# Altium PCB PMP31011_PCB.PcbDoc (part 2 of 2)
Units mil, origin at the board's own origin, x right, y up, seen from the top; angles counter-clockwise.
Board outline 3287.4 x 3750 mil, 4 copper layers (Top Layer, GND, Signal Layer, Bottom Layer), stack 84.834 mil thick; 100 components, 44 nets, 235 pads, 404 vias.
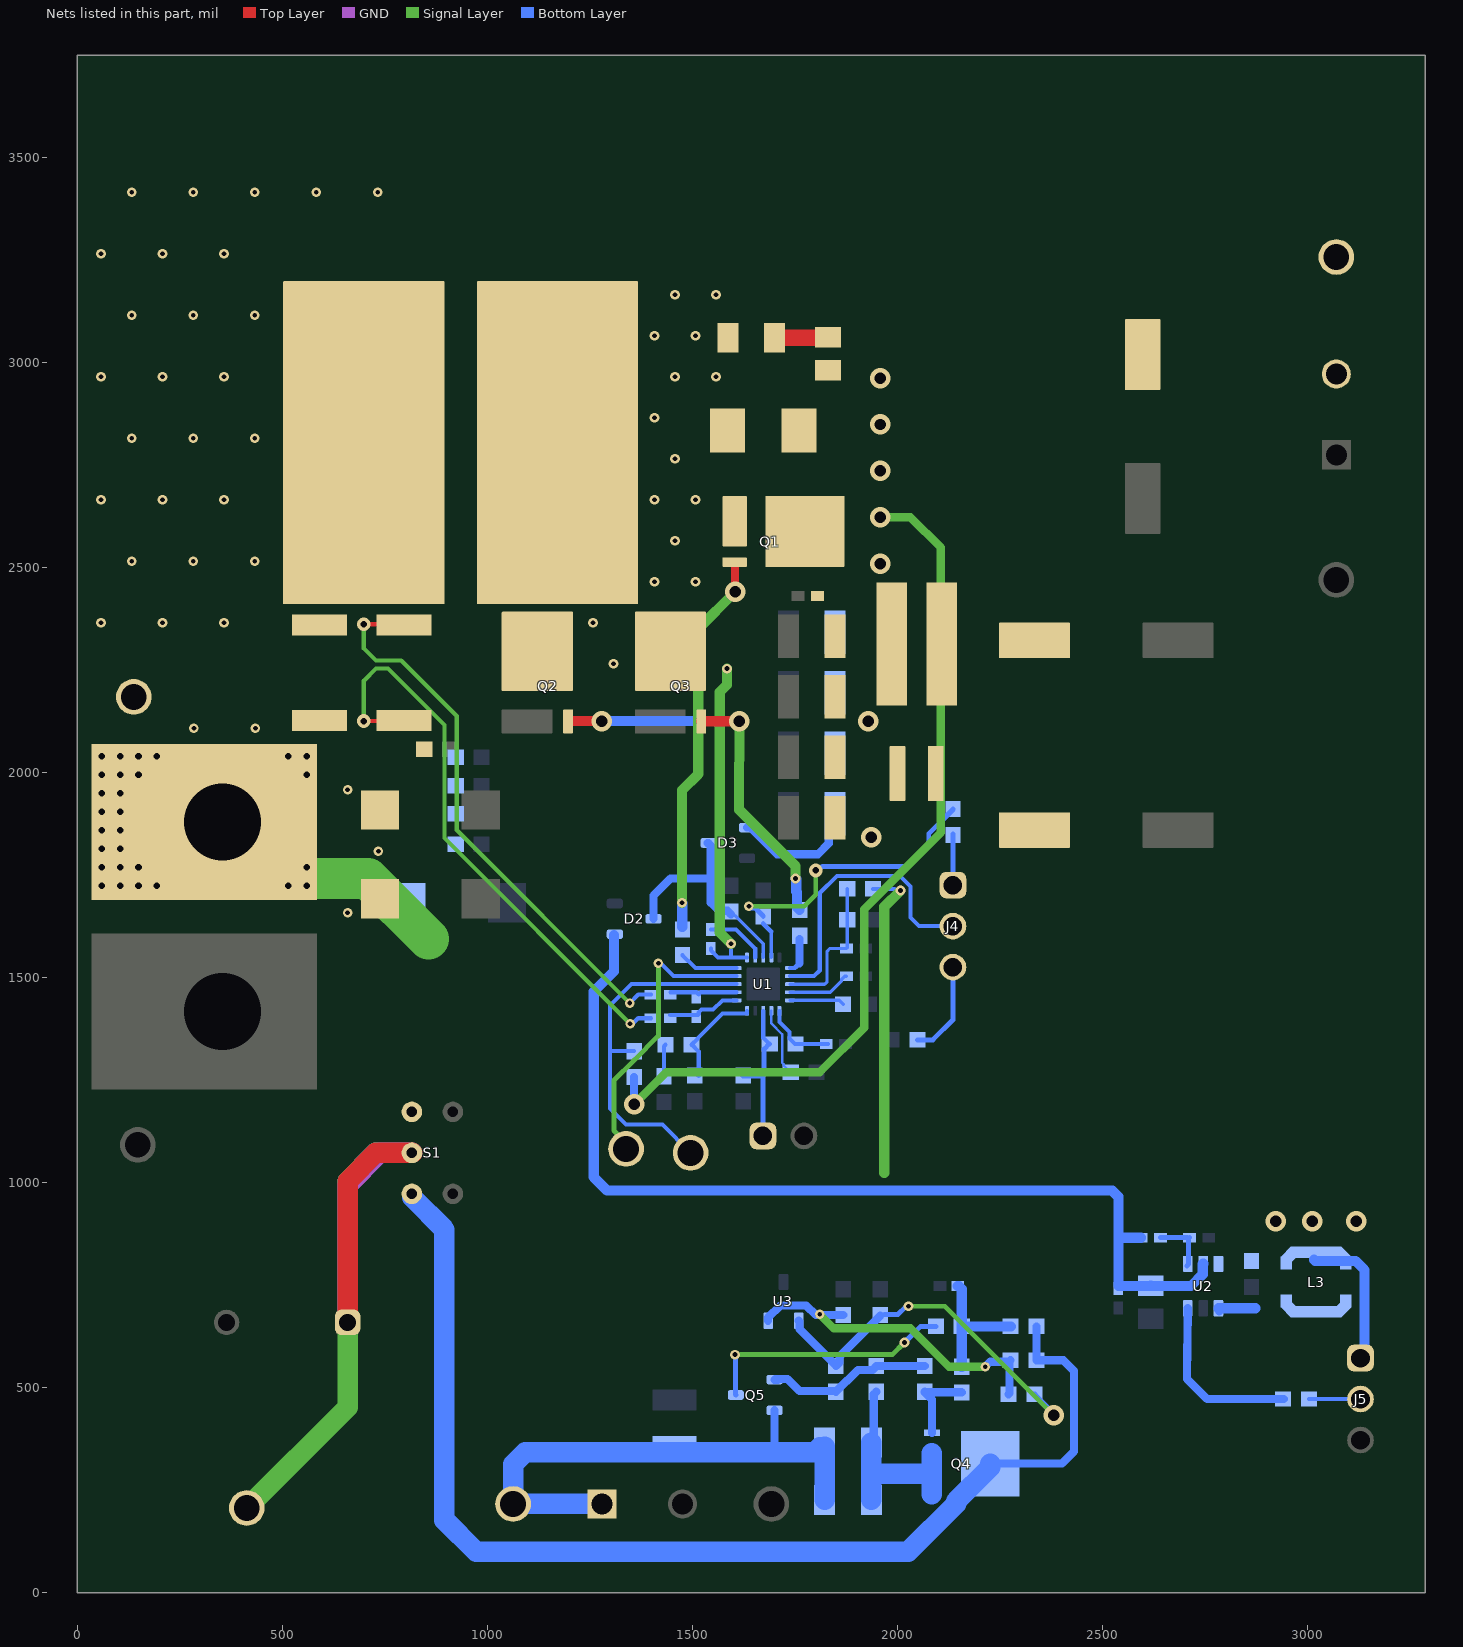
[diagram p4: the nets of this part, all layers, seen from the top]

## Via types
v1: diameter 23.62, hole 11.81, Top Layer to Bottom Layer, 298 vias
v2: diameter 32, hole 16, Top Layer to Bottom Layer, 56 vias
v3: diameter 50, hole 28, Top Layer to Bottom Layer, 37 vias
v4: diameter 23.62, hole 11.81, Top Layer to Bottom Layer, tented both sides, 6 vias
v5: diameter 196.85, hole 118.11, Top Layer to Bottom Layer, 4 vias
v6: diameter 34, hole 16, Top Layer to Bottom Layer, 3 vias

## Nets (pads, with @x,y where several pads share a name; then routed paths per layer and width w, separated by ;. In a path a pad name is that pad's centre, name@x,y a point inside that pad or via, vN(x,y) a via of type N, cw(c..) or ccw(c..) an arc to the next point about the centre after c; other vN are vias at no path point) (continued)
CSN: L2.1 R2.1 R3.1 R11.2 | length 1394.2
  Top Layer w10: v6(698.82,2362.2) R3.1@797.24,2362.2
  Signal Layer w10: v6@703.41,2357.61 v6(698.82,2362.2) 698.82,2303.15 728.35,2273.62 790.28,2273.62 925.54,2138.36 925.54,1859.89 v1(1347.38,1438.06)
  Bottom Layer w10: v1(1347.38,1438.06) 1347.64,1438.06 1368.3,1458.71 R11.2@1399.05,1458.71
  other v1: 58,2366 208,2366 358,2366 133,2516 283,2516 433,2516 58,2666 208,2666 358,2666 133,2816 283,2816 433,2816 58,2966 208,2966 358,2966 133,3116 283,3116 433,3116 58,3266 208,3266 358,3266 133,3416 283,3416 433,3416 583,3416 733,3416
CSP: C2.1 C3.1 C4.1 C5.1 C6.1 C7.1 C8.1 C9.1 C34.1 J5.1 L3.1 R2.2 R3.2 R6.2 R10.2 S1.4 T1.1 TP1.1 U2.6 | length 3118.8
  Top Layer w10: v6(698.82,2125.98) R3.2@797.24,2125.98
  Signal Layer w10: v6(698.82,2125.98) 698.82,2224.41 728.35,2253.94 757.87,2253.94 895.67,2116.14 895.67,1840.55 v1(1348.43,1387.8)
  Signal Layer w25: 1968.5,1023.62 1968.5,1673.23 v1(2007.87,1712.6)
  Signal Layer w100: T1.1@481.3,1742.13 708.66,1742.13 856.3,1594.49
  Bottom Layer w10: v1(1348.43,1387.8) 1354.8,1387.8 1368.3,1401.29 R10.2@1399.05,1401.29 ; R6.2@1940.95,1716.75 1993.88,1716.75 1998.03,1712.6 v1(2007.87,1712.6)
  Bottom Layer w25: 3016.76,812.03 3019.41,809.38 3117.79,809.38 3139.76,787.4 J5.1@3139.76,572.44 ; J5.1@3129.92,570.87 J5.1@3129.92,572.44
  Bottom Layer w50: T1.1@344.49,1878.94 T1.1@432.09,1791.34
  other v1: 659.45,1658.66 734.45,1808.66 659.45,1958.66 284.45,2108.66 434.45,2108.66
  other v2: 59.33,1724.92 104.33,1724.92 149.33,1724.92 194.33,1724.92 514.33,1724.92 559.33,1724.92 59.33,1769.92 104.33,1769.92 149.33,1769.92 559.33,1769.92 59.33,1814.92 104.33,1814.92 59.33,1859.92 104.33,1859.92 59.33,1904.92 104.33,1904.92 59.33,1949.92 104.33,1949.92 59.33,1994.92 104.33,1994.92 149.33,1994.92 559.33,1994.92 59.33,2039.92 104.33,2039.92 149.33,2039.92 194.33,2039.92 514.33,2039.92 559.33,2039.92
  other v3: 2923.23,905.51 3011.81,905.51 3120.08,905.51
HO: R5.1 U1.5 | length 145.5
  Bottom Layer w10: R5.1@1476.38,1555.12 1476.38,1554.13 1490.08,1540.43 1491.06,1540.43 1507.82,1523.68 U1.5@1608.27,1523.68
MODE: J4.2 U1.12 | length 694.9
  Bottom Layer w10: U1.12@1738.19,1503.99 1797.3,1503.99 1811.02,1517.72 1811.02,1706.41 1852.94,1748.32 2007.06,1748.32 2032.56,1722.82 2032.56,1646.53 2053.1,1625.98 J4.2@2125.98,1625.98
NetC1_2: C1.2 R1.2 | length 119.6
  Top Layer w25: R1.2@1700.79,3061.02 1700.79,3050.2 R1.2@1701.13,3049.79
  Top Layer w40: R1.2@1722.44,3061.02 C1.2@1830.71,3061.02
NetC22_1: C22.1 D2.3 D3.3 U1.8 | length 556.7
  Bottom Layer w8: C22.1@1604.33,1651.63 1673.23,1582.73 U1.8@1673.23,1549.27
  Bottom Layer w20: D2.3@1405.51,1643.7 1405.51,1700.79 1446.85,1742.13 1545.28,1742.13 ; D3.3@1539.37,1828.74 1537.4,1828.74 1545.28,1820.87 1545.28,1742.13 ; C22.1@1594.49,1654.68 1585.79,1663.39 1564.96,1663.39 1545.28,1683.07 1545.28,1742.13
NetC23_1: C23.1 U1.7 | length 149.7
  Bottom Layer w10: C23.1@1545.28,1618.16 1606.73,1618.16 1653.54,1571.35 U1.7@1653.54,1549.27
NetC23_2: C23.2 D1.2 L2.2 Q1.1-2-3 Q2.5-6-7-8 Q3.5-6-7-8 R1.1 U1.6 | length 825.8
  Signal Layer w25: v1(1584.65,2253.94) 1584.65,2214.57 1566.96,2196.88 1566.96,1610.26 v1(1594.49,1582.73)
  Bottom Layer w10: C23.2@1545.28,1570.92 1545.28,1566.98 1562.99,1549.27 U1.6@1633.86,1549.27 ; v1@1589.9,1578.14 v1(1594.49,1582.73) 1594.49,1553.2
  other v1: 1308,2266 1258,2366 1408,2466 1508,2466 1458,2566 1408,2666 1508,2666 1458,2766 1408,2866 1458,2966 1558,2966 1408,3066 1508,3066 1458,3166 1558,3166
NetC24_1: C24.1 R6.1 R9.2 U1.13 | length 363.8
  Bottom Layer w8: U1.13@1738.19,1484.31 1822.68,1484.31 1828.74,1490.37 1828.74,1564.96 1835.13,1571.35 C24.1@1875.98,1571.35 1877.95,1573.32 R9.2@1877.95,1641.79 R6.1@1877.95,1716.75
NetC25_1: C25.1 S1.5 TP6.1 | length 2659.5
  Top Layer w50: C25.1@659.45,669.29 659.45,1003.94 728.35,1072.83 S1.5@816.14,1072.83 S1.5@816.93,1072.83
  GND w50: C25.1@659.45,659.45 659.45,994.09 738.19,1072.83 S1.5@816.14,1072.83
  Signal Layer w50: TP6.1@413.39,196.85 TP6.1@423.23,196.85 ; TP6.1@413.39,206.69 659.45,452.76 C25.1@659.45,659.45 659.45,1003.94 728.35,1072.83 S1.5@816.14,1072.83
  Bottom Layer w50: C25.1@659.45,669.29 659.45,1003.94 728.35,1072.83 S1.5@816.14,1072.83 S1.5@816.93,1072.83
NetC26_1: C26.1 R10.1 U1.1 | length 179
  Bottom Layer w10: R10.1@1446.29,1409.5 1513.78,1409.5 1515.75,1411.47 1515.75,1415.41 1522.56,1422.22 1550.65,1422.22 1573.37,1444.93 U1.1@1608.27,1444.93
NetC26_2: C26.2 R11.1 U1.2 | length 166.3
  Bottom Layer w10: R11.1@1446.85,1464.62 1509.84,1464.62 1515.75,1458.71 1521.65,1464.62 U1.2@1608.27,1464.62
NetC27_1: C27.1 U1.17 | length 171.8
  Bottom Layer w6: U1.17@1692.91,1419.34 1692.91,1388.41 1719.54,1361.79 1719.54,1292.28 1723.47,1288.34 1723.47,1285.39 1739.17,1269.68 C27.1@1740.16,1269.68 C27.1@1742.13,1269.68
NetC29_1: C29.1 R13.2 U1.20 | length 258.5
  Bottom Layer w10: R13.2@1497.84,1336.67 R13.2@1498.82,1336.67 ; C29.1@1515.75,1259.9 1515.75,1319.74 R13.2@1498.82,1336.67 ; U1.20@1633.86,1419.34 1633.86,1412.81 1633.58,1412.53 1573.71,1412.53 1512.52,1351.35 1512.52,1350.37 R13.2@1498.82,1336.67
NetC30_1: C30.1 R16.2 U1.16 | length 175.4
  Bottom Layer w10: U1.16@1712.6,1419.34 1712.6,1392.53 1737.28,1367.85 1737.28,1352.28 R16.2@1750.98,1338.58 ; R16.2@1751.97,1338.58 C30.1@1826.77,1338.58 C30.1@1830.71,1338.58
NetC31_1: C31.1 R13.1 | length 78.3
  Bottom Layer w10: C31.1@1431.1,1259.9 1431.1,1332.92 R13.1@1434.85,1336.67
NetC32_1: C32.1 J2.1 Q5.2 R15.1 R17.1 TP7.1 | length 1331.3
  Bottom Layer w20: Q5.2@1700.79,444.88 1700.79,350.39 1708.66,342.52
  Bottom Layer w25: R15.1@1822.83,355.61 R15.1@1822.83,366.14
  Bottom Layer w50: TP7.1@1062.99,216.54 J2.1@1279.53,216.54 ; TP7.1@1062.99,221.13 1062.99,313.23 1092.28,342.52 1708.66,342.52 1799.21,342.52 1811.42,354.72 1822.24,354.72 R15.1@1822.83,355.32 ; R17.1@1822.83,226.38 R15.1@1822.83,355.32 ; R15.1@1822.83,355.61 R15.1@1822.83,355.32
NetC33_1: C33.1 C37.1 R23.1 U3.1 | length 918.6
  Signal Layer w12: v1(2027.56,698.82) 2116.14,698.82 v3(2381.89,433.07)
  Bottom Layer w12: C37.1@1968.5,679.13 2001.92,679.13 2021.61,698.82 v1(2027.56,698.82) ; C33.1@2334.65,484.25 2335.63,484.25 2381.89,437.99 v3(2381.89,433.07)
  Bottom Layer w20: U3.1@1759.84,663.39 1761.65,661.57 1761.65,642.87 1850.39,554.13 R23.1@1850.39,553.15 1859.09,561.85 1859.09,576.61 C37.1@1958.66,676.18
NetC33_2: C33.2 R22.1 R29.2 U3.2 | length 810
  Signal Layer w20: v1(1811.02,679.13) 1845.05,645.11 2032.16,645.11 2126.09,551.18 v1(2214.57,551.18)
  Bottom Layer w20: U3.2@1685.04,663.39 1685.04,671.26 1714.72,700.95 1777.88,700.95 v1@1801.66,677.17 ; v1@1811.02,677.17 R29.2@1868.11,677.17 ; v1(2214.57,551.18) 2226.89,563.5 2273.15,563.5 R22.1@2274.11,564.47 ; C33.2@2271.65,484.25 2274.11,486.71 R22.1@2274.11,564.47 ; R22.1@2276.57,566.93 R22.1@2274.11,564.47
NetD4_1: D4.1 R21.1 R24.1 R25.2 | length 321.5
  Bottom Layer w25: D4.1@2147.64,748.03 2150.2,748.03 2157.48,740.75 R25.2@2157.48,649.61 ; R24.1@2157.48,551.18 R25.2@2157.48,649.61 ; R21.1@2276.57,649.61 R25.2@2157.48,649.61
NetJ3_1: J3.1 R16.1 R20.2 U1.18 | length 372
  Bottom Layer w10: U1.18@1673.23,1419.34 1673.23,1353.35 1687.99,1338.58 R16.1@1688.98,1338.58
  Bottom Layer w12: R20.2@1624.02,1259.84 1673.23,1259.84 ; 1671.26,1263.78 1672.44,1262.6 ; J3.1@1673.23,1114.17 1672.44,1114.96 1672.44,1262.6 ; 1673.23,1261.81 1672.44,1262.6 ; R16.1@1688.98,1338.58 1687.99,1338.58 1675.29,1325.88 1675.29,1265.45 1672.44,1262.6
NetJ4_1: J4.1 R30.1 | length 124.4
  Bottom Layer w12: J4.1@2135.83,1725.98 R30.1@2135.83,1848.43 R30.1@2135.83,1850.39
NetJ4_3: J4.3 R32.2 | length 239.6
  Bottom Layer w12: R32.2@2049.21,1348.43 2086.9,1348.43 2135.83,1397.35 2135.83,1516.14 J4.3@2125.98,1525.98
NetJ5_2: J5.2 R26.2 | length 126
  Bottom Layer w10: R26.2@3003.94,472.44 J5.2@3129.92,472.44
NetL3_2: L3.2 U2.1 | length 97.7
  Bottom Layer w20: U2.1@2783.46,693.9 2783.46,688.49 U2.1@2785.28,686.68
  Bottom Layer w25: U2.1@2783.46,693.9 2873.23,693.9
NetQ1_4: Q1.4 R5.2 | length 944
  Top Layer w20: Q1.4@1603.54,2513.58 1603.94,2513.19 1603.94,2441.34 v3(1604.33,2440.94)
  Signal Layer w25: v1(1475.03,1683.07) 1475.03,1957.32 1514.4,1996.68 1514.4,2351.01 v3(1604.33,2440.94)
  Bottom Layer w25: v1(1475.03,1683.07) 1475.7,1682.4 1475.7,1624.69 R5.2@1476.38,1624.02
NetQ2_4: Q2.4 Q3.4 R8.1 | length 1028.4
  Top Layer w25: Q2.4@1200.79,2125.98 v3(1279.53,2125.98) ; Q3.4@1521.85,2125.2 1522.24,2125.59 1613.78,2125.59 v3(1614.17,2125.98)
  Signal Layer w25: v3(1614.17,2125.98) 1615.52,2124.63 1614.17,1929.13 1614.17,1909.45 1751.97,1771.65 v1(1751.97,1742.13)
  Bottom Layer w25: v3(1279.53,2125.98) v3(1614.17,2125.98) ; v1(1751.97,1742.13) 1753.69,1740.4 1753.69,1710.88 1755.61,1708.96 1755.61,1671.56 R8.1@1761.81,1665.35
NetQ4_1: Q4.1 Q4.2 Q4.3 R15.2 R17.2 R18.2 | length 516.1
  Bottom Layer w20: R15.2@1937.01,366.14 1942.91,372.05 1942.91,484.25 R18.2@1948.82,490.16
  Bottom Layer w50: R17.2@1937.01,226.38 1937.01,289.96 ; R15.2@1937.01,366.14 1937.01,289.96 ; Q4.1@2084.45,239.96 Q4.2@2084.45,289.96 ; Q4.3@2084.45,339.96 Q4.2@2084.45,289.96 ; 1937.01,289.96 Q4.2@2084.45,289.96
NetQ4_4: Q4.4 R19.2 R24.2 | length 198.8
  Bottom Layer w20: Q4.4@2084.45,389.96 2084.45,471.65 2066.93,489.17 R19.2@2066.93,490.16 2067.91,489.17 2156.5,489.17 R24.2@2157.48,488.19
NetQ4_5: Q4.5 R21.2 R22.2 S1.6 | length 2879
  Bottom Layer w20: Q4.5@2226.57,314.96 2401.57,314.96 2431.1,344.49 2431.1,541.34 2405.51,566.93 R22.2@2339.57,566.93 R21.2@2339.57,649.61
  Bottom Layer w50: S1.6@816.93,964.57 895.67,885.83 895.67,551.18 895.57,177.27 972.84,100 2026.33,100 2143.78,217.44 2143.78,223.68 2226.57,306.48 Q4.5@2226.57,314.96
NetQ5_1: Q5.1 R18.1 R19.1 R23.2 | length 411.5
  Bottom Layer w20: Q5.1@1700.79,519.69 Q5.1@1708.66,519.69 ; Q5.1@1702.76,521.65 1732.28,521.65 1761.81,492.13 R23.2@1850.39,492.13 ; R23.2@1850.39,490.16 1850.39,491.14 1874.84,515.59 1876.5,515.59 1904.37,543.46 1940.12,543.46 1948.82,552.17 R18.1@1948.82,553.15 R19.1@2066.93,553.15
NetQ5_3: Q5.3 R25.1 | length 617.9
  Signal Layer w12: v1(1604.33,580.71) 1988.19,580.71 v1(2017.72,610.24)
  Bottom Layer w12: v1(1604.33,580.71) 1605.32,579.72 1605.32,483.27 Q5.3@1606.3,482.28 ; v1(2017.72,610.24) 2057.09,649.61 R25.1@2094.49,649.61
NetR7_1: R7.1 TP5.1 U1.3 | length 883.3
  Bottom Layer w10: R7.1@1358.27,1320.87 1301.18,1320.87 1299.21,1318.9 ; TP5.1@1496.06,1072.83 1427.17,1141.73 1338.58,1141.73 1299.21,1181.1 1299.21,1318.9 ; U1.3@1608.27,1484.31 1351.38,1484.31 1299.21,1432.14 1299.21,1318.9
NetR8_2: R8.2 U1.11 | length 87.5
  Bottom Layer w10: U1.11@1738.19,1523.68 1738.46,1523.95 1750.33,1523.95 1751.97,1525.59
  Bottom Layer w12: 1751.97,1525.59 1761.81,1535.43
  Bottom Layer w20: 1761.81,1535.43 R8.2@1761.81,1594.49
NetR12_2: R12.2 U1.15 | length 134
  Bottom Layer w8: U1.15@1738.19,1444.93 1858.27,1444.93 R12.2@1868.11,1435.09
NetR14_2: R14.2 U1.14 | length 156.4
  Bottom Layer w8: U1.14@1738.19,1464.62 1836.61,1464.62 1864.24,1492.24 1864.24,1496.18 1872.05,1503.99 R14.2@1875.98,1503.99
NetR26_1: R26.1 U2.3 | length 428.9
  Bottom Layer w20: U2.3@2708.66,693.9 2706.69,521.65 2755.91,472.44 R26.1@2940.94,472.44 R26.1@2942.91,472.44
NetR28_1: R28.1 R31.2 U2.4 | length 136.3
  Bottom Layer w12: R28.1@2641.73,866.14 R31.2@2706.69,866.14 ; U2.4@2706.69,797.24 2710.63,801.18 2710.63,864.17 R31.2@2712.6,866.14
STATUS: TP9.1 U1.4 | length 776.8
  Top Layer w20: TP9.1@1338.58,1053.15 TP9.1@1338.58,1082.68
  Signal Layer w12: TP9.1@1331.2,1082.68 1331.2,1105.06 1309.06,1127.21 1309.06,1250 1358.27,1299.21 1417.32,1358.27 v1(1417.32,1535.43) ; TP9.1@1338.58,1072.83 TP9.1@1338.58,1082.68
  Signal Layer w20: TP9.1@1338.58,1053.15 1351.15,1065.71 TP9.1@1365.39,1065.71
  Bottom Layer w10: v1@1422.67,1535.49 1454.16,1503.99 U1.4@1608.27,1503.99
VAUX: C35.1 C36.1 D2.1 R28.2 U2.5 | length 2427
  Bottom Layer w25: D2.1@1309.06,1604.33 1309.06,1515.75 1259.84,1466.54 1259.84,1013.78 1292.72,980.91 2524.73,980.91 2539.37,966.26 2539.37,866.14 ; R28.2@2594.49,866.14 2539.37,866.14 ; C36.1@2618.11,748.03 2716.54,748.03 2745.37,776.87 2745.37,801.48 U2.5@2746.06,802.17 ; C36.1@2618.11,748.66 2539.37,748.03 2539.37,866.14
VCC: C28.1 R30.2 U1.9 | length 786.4
  Signal Layer w12: v1(1638.06,1674.32) 1772.75,1674.32 1801.18,1702.76 v6(1801.18,1761.81)
  Bottom Layer w8: 1692.72,1612.26 1692.91,1612.07 U1.9@1692.91,1549.27
  Bottom Layer w12: v1(1638.06,1674.32) 1642.27,1670.11 1653.76,1670.11 1673.23,1650.64 C28.1@1673.23,1649.66 ; C28.1@1673.23,1631.94 1692.72,1612.45 1692.72,1612.26 ; v6@1801.18,1771.65 1806.81,1766.02 1811.34,1766.02 1816.98,1771.65 2027.56,1771.65 2076.77,1820.87 2076.77,1851.38 2135.83,1910.43 R30.2@2135.83,1911.42
VOUT: C1.1 C10.1 C11.1 C12.1 C13.1 C14.1 C15.1 C16.1 C17.1 C18.1 D1.1 D3.1 L1.1 Q1.5-6-7-8 R4.1 R7.2 | length 2438.8
  Signal Layer w20: v3(1358.27,1190.94) 1399.31,1231.99 1437.01,1269.68 1811.02,1269.68 1919.29,1377.95 1919.29,1666.97 2106.3,1853.98 2106.3,2549.21 2032.48,2623.03 v3(1958.66,2623.03)
  Bottom Layer w20: v3(1358.27,1190.94) R7.2@1358.27,1257.87 ; D3.1@1633.86,1866.14 1641.73,1866.14 1706.69,1801.18 1806.79,1801.18 1832.83,1827.23 1832.83,1872.2 C18.1@1850.39,1889.76
  other v3: 1936.94,1842.59 1929.13,2125.98 1958.66,2509.84 1958.66,2736.22 1958.66,2849.41 1958.66,2962.6
VOUT_FLT: C19.2 C20.2 C21.2 J1.2 L1.2 R4.2 TP2.1
pads on no net: D2.2 D3.2 S1.1 S1.3
copper on no net:
  other v3: 2145.67,3336.61
  other v5: 147.64,147.64 3139.76,147.64 147.64,3602.36 3139.76,3602.36

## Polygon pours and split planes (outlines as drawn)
NetC23_2 on Top Layer "TOP_LAYER_NETC23_2_P010" (solid, pour order 10): 974.41,3248.03 1003.94,3277.56 1604.33,3277.56 1633.86,3248.03 1633.86,2480.32 1614.17,2460.63 1614.17,2234.25 1564.96,2185.04 1043.31,2185.04 974.41,2253.94
CSP on Top Layer "TOP_LAYER_CSP_P004" (solid, remove dead copper, pour order 4): 19.68,2234.25 39.37,2253.94 787.4,2253.94 866.14,2175.2 866.14,1690.55 798.24,1643.7 29.53,1643.7 29.53,2057.08 19.69,2057.08
CSN on Top Layer "TOP_LAYER_CSN_P009" (solid, pour order 9): 885.83,2372.05 885.83,2322.83 859.25,2296.26 56.1,2296.26 29.53,2322.83 29.53,3533.46 78.74,3582.68 836.61,3582.68 885.83,3533.46
NetC1_2 on Top Layer "TOP_LAYER_NETC1_2_P011" (solid, pour order 11): 1673.23,3553.15 1702.76,3582.68 1988.19,3582.68 2037.4,3533.47 2037.4,3051.18 2007.87,3021.65 1673.23,3021.65
VOUT_FLT on Top Layer "TOP_LAYER_VOUT_FLT_P002" (solid, pour order 2): 2062.95,3405.51 3080.71,3405.51 3149.61,3336.61 3149.61,2864.17 2578.74,2864.17 2500,2785.43 2500,1692.91 2460.63,1653.54 2096.42,1653.54 2062.95,1687.01
VOUT on Top Layer "TOP_LAYER_VOUT_P003" (solid, pour order 3): 1673.23,2981.65 1703.23,3011.65 2007.79,3011.65 2031.53,2987.91 2031.53,1797.81 2005.37,1771.65 1821.02,1771.65 1791.49,1801.18 1791.49,2460.48 1774.75,2477.22 1692.74,2477.22 1673.23,2496.73
AGND on Top Layer "TOP_LAYER_AGND_P023" (solid, pour order 23): 2716.54,3385.83 2401.57,3385.83 2342.52,3385.83 2234.25,3385.83 2214.57,3366.14 2214.57,3051.18 2165.35,3001.97 2057.09,3001.97 2057.09,2480.32 1690.95,2480.32 1633.86,2419.15 1633.86,2165.35 1624.02,2155.51 925.2,2155.51 885.83,2116.14 885.83,1675.71 810.14,1614.17 19.68,1614.17 19.68,108.27 68.9,59.06 68.9,39.37 3188.98,39.37 3248.03,98.43 3248.03,3287.4 3149.61,3385.83
NetC23_2 on Bottom Layer "BOTTOM_LAYER_NETC23_2_P013" (solid, pour order 13): 974.41,3248.03 1003.94,3277.56 1604.33,3277.56 1633.86,3248.03 1633.86,2480.32 1614.17,2460.63 1614.17,2234.25 1564.96,2185.04 1043.31,2185.04 974.41,2253.94
CSN on Bottom Layer "BOTTOM_LAYER_CSN_P015" (solid, pour order 15): 885.83,2372.05 885.83,2322.83 859.25,2296.26 56.1,2296.26 29.53,2322.83 29.53,3533.46 78.74,3582.68 836.61,3582.68 885.83,3533.46
AGND on Bottom Layer "BOTTOM_LAYER_AGND_P053" (solid, remove dead copper, pour order 53): 2716.54,3385.83 2401.57,3385.83 2342.52,3385.83 2234.25,3385.83 2214.57,3366.14 2214.57,3051.18 2165.35,3001.97 2057.09,3001.97 2057.09,2480.32 1690.95,2480.32 1633.86,2419.15 1633.86,2165.35 1624.02,2155.51 1003.94,2155.51 966.54,2118.11 966.54,1685.04 895.67,1614.17 19.68,1614.17 19.68,108.27 68.9,59.06 68.9,39.37 3188.98,39.37 3248.03,98.43 3248.03,3287.4 3149.61,3385.83
CSP on Bottom Layer "BOTTOM_LAYER_CSP_P019" (solid, pour order 19): 2775.59,777.56 2775.59,836.61 2834.65,836.61 2864.17,866.14 2864.17,935.04 2893.7,964.57 3159.45,964.57 3198.82,925.2 3198.82,787.4 3179.13,767.72 2785.43,767.72
AGND on Bottom Layer "BOTTOM_LAYER_AGND_P047" (solid, pour order 47): 2490.16,1210.63 2529.53,1250 3208.66,1250 3248.03,1210.63 3248.03,344.49 3198.82,295.28 2559.06,295.28 2490.16,364.17
NetL3_2 on Bottom Layer "BOTTOM_LAYER_NETL3_2_P025" (solid, pour order 25): 2775.59,718.5 2844.49,718.5 2864.17,738.19 3120.08,738.19 3120.08,659.45 3100.39,639.76 2864.17,639.76 2824.8,679.13 2775.59,679.13
AGND on Bottom Layer "BOTTOM_LAYER_AGND_P043" (solid, remove dead copper, pour order 43): 9.84,1614.17 885.83,1614.17 954.72,1683.07 954.72,2116.14 3248.03,2116.14 3248.03,1683.07 1811.02,1683.07 1811.02,1446.85 1781.5,1417.32 1377.95,1417.32 1358.27,1397.64 1358.27,836.61 1289.37,836.61 1141.73,688.98 1141.73,59.06 1102.36,19.68 49.21,19.68 9.84,59.06
AGND on Bottom Layer "BOTTOM_LAYER_AGND_P005" (solid, pour order 5): 1643.7,1438.98 1663.39,1438.98 1663.39,1311.02 1791.34,1311.02 1820.87,1340.55 1820.87,1663.39 1840.55,1683.07 1968.5,1683.07 1988.19,1663.39 1988.19,1015.75 1958.66,986.22 1417.32,986.22 1377.95,1025.59 1377.95,1281.5 1397.64,1301.18 1545.28,1301.18 1643.7,1399.61
CSP on Bottom Layer "BOTTOM_LAYER_CSP_P024" (solid, remove dead copper, pour order 24): 29.53,2244.09 29.53,1663.39 68.9,1624.02 895.67,1624.01 944.88,1673.23 944.88,2165.35 856.3,2253.94 39.37,2253.94
AGND on Bottom Layer "BOTTOM_LAYER_AGND_P040" (solid, pour order 40): 19.68,3651.57 98.43,3730.31 3188.98,3730.31 3257.87,3661.42 3248.03,3651.57 3248.03,1574.8 3179.13,1505.91 2145.67,1505.91 2076.77,1574.8 2076.77,2657.48 2027.56,2706.69 1643.7,2706.69 1643.7,2076.77 669.29,2076.77 482.28,2263.78 59.06,2263.78 19.68,2303.15
AGND on Bottom Layer "BOTTOM_LAYER_AGND_P029" (solid, pour order 29): 1624.02,2696.85 1643.7,2716.54 1771.65,2716.53 1791.34,2696.85 1791.34,1830.71 1761.81,1801.18 1653.54,1801.18 1624.02,1830.71
VOUT on Bottom Layer "BOTTOM_LAYER_VOUT_P016" (solid, pour order 16): 1801.18,2972.44 1830.71,3001.97 2007.87,3001.97 2047.24,2962.6 2047.24,1830.71 2007.87,1791.34 1801.18,1791.34
AGND on Bottom Layer "BOTTOM_LAYER_AGND_P028" (solid, pour order 28): 1293.29,801.16 2437.02,801.16 2450.79,787.4 2450.79,177.17 2362.2,88.58 1210.63,88.58 1161.42,137.8 1161.42,669.29
NetC23_2 on GND "GND_NETC23_2_P038" (solid, pour order 38): 974.41,3248.03 1003.94,3277.56 1604.33,3277.56 1633.86,3248.03 1633.86,2480.32 1614.17,2460.63 1614.17,2234.25 1564.96,2185.04 1043.31,2185.04 974.41,2253.94
AGND on GND "GND_AGND_P051" (solid, remove dead copper, pour order 51): 9.84,3720.47 3248.03,3720.47 3248.03,39.37 3257.87,29.53 9.84,29.53
CSN on GND "GND_CSN_P045" (solid, pour order 45): 885.83,2372.05 885.83,2322.83 859.25,2296.26 56.1,2296.26 29.53,2322.83 29.53,3533.46 78.74,3582.68 836.61,3582.68 885.83,3533.46
CSP on GND "GND_CSP_P041" (solid, remove dead copper, pour order 41): 19.68,2234.25 19.69,2234.25 39.37,2253.94 856.3,2253.94 925.2,2185.04 925.2,1676.97 876.98,1643.7 29.53,1643.7 29.53,2057.08 19.69,2057.08
CSP on Signal Layer "SIGNAL_LAYER_CSP_P030" (solid, pour order 30): 1279.53,1043.31 1279.53,1437.01 875.98,1840.55 875.98,2096.46 718.5,2253.94 39.37,2253.94 19.68,2234.25 19.68,1692.91 59.06,1653.54 590.55,1653.54 610.24,1633.86 610.24,1092.52 610.24,19.68 3188.98,19.68 3257.87,88.58 3257.87,984.25 3198.82,1043.31
NetC23_2 on Signal Layer "SIGNAL_LAYER_NETC23_2_P027" (solid, pour order 27): 974.41,3248.03 1003.94,3277.56 1604.33,3277.56 1633.86,3248.03 1633.86,2480.32 1614.17,2460.63 1614.17,2234.25 1564.96,2185.04 1043.31,2185.04 974.41,2253.94
CSN on Signal Layer "SIGNAL_LAYER_CSN_P042" (solid, pour order 42): 885.83,2372.05 885.83,2322.83 859.25,2296.26 56.1,2296.26 29.53,2322.83 29.53,3533.46 78.74,3582.68 836.61,3582.68 885.83,3533.46
AGND on Signal Layer "SIGNAL_LAYER_AGND_P052" (solid, remove dead copper, pour order 52): 19.68,1072.83 19.68,78.74 68.9,29.53 580.71,29.53 580.71,1072.83 3248.03,1072.83 3248.03,3287.4 3149.61,3385.83 2716.54,3385.83 2401.57,3385.83 2234.25,3385.83 2214.57,3366.14 2214.57,3051.18 2165.35,3001.97 2057.09,3001.97 2057.09,2480.32 1690.95,2480.32 1633.86,2419.15 1633.86,2165.35 1624.02,2155.51 1003.94,2155.51 966.54,2118.11 966.54,1685.04 895.67,1614.17 19.68,1614.17
AGND on Signal Layer "SIGNAL_LAYER_AGND_P046" (solid, remove dead copper, pour order 46): 33.84,3586.69 102.73,3655.59 102.73,3675.27 3203.13,3675.27 3252.34,3626.06 3252.34,1067.01 3193.28,1007.95 1047.61,1007.95 988.56,1067.01 988.56,1992.2 939.35,2041.41 663.76,2041.41 447.22,2257.95 63.36,2257.95 33.84,2287.48

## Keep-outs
Keep-Out Layer:
  text ".Layer_Name" at 577,-858.49 h60

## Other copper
Top Layer:
  pour cut-out: 1722.44,1161.42 1830.71,1161.42 1830.71,1062.99 1722.44,1062.99
  text ".Layer_Name" at 577,-858.49 h60
GND:
  pour cut-out: 1722.44,1161.42 1830.71,1161.42 1830.71,1062.99 1722.44,1062.99
Signal Layer:
  pour cut-out: 679.13,2372.05 688.98,2381.89 708.66,2381.89 728.35,2362.2 728.35,2273.62 679.13,2273.62
  pour cut-out: 797.24,2283.46 797.24,2204.72 718.5,2204.72 718.5,2116.14 708.66,2106.3 688.98,2106.3 679.13,2116.14 679.13,2283.46
  pour cut-out: 1722.44,1161.42 1830.71,1161.42 1830.71,1062.99 1722.44,1062.99
Bottom Layer:
  pour cut-out: 1988.19,1013.78 1377.95,1013.78 1387.8,1023.62 1387.8,1358.27 1368.11,1358.27 1368.11,1003.94 1988.19,1003.94
  pour cut-out: 1909.45,1692.91 2007.87,1692.91 2007.87,1003.94 1988.19,1003.94 1988.19,1673.23 1909.45,1673.23
  text ".Layer_Name" at 577,-858.49 h60

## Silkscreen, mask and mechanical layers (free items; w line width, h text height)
Top Overlay:
  text "VOUT" at 3218.5,3090.55 h72.83 r90
  text "GND" at 3228.35,2519.68 h72.83 r90
  text "VIN" at 305.12,2086.61 h72.83
  text "1:2 FPWM / -     Skip / 2:3 DEM" at 1771.65,1536.38 h72.83
  text "GND" at 226.38,1151.57 h72.83
  text "CHARGE  VIN" at 1013.78,777.56 h72.83 r90
  text "Disable Enable" at 3228.35,295.28 h60 r90
  text "SuperCap Charge" at 639.76,72.71 h72.83
  text "GND" at 1633.86,59.84 h72.83
  text "PMP31011 RevA" at 2263.78,49.21 h108.27
  text ".Layer_Name" at 577,-858.49 h60
Bottom Overlay:
  text ".Layer_Name" at 577,-858.49 h60
Top Paste:
  text ".Layer_Name" at 577,-858.49 h60
Bottom Paste:
  text ".Layer_Name" at 577,-858.49 h60
Top Solder:
  text ".Layer_Name" at 577,-858.49 h60
  text ".Layer_Name" at 577,-858.49 h60
Bottom Solder:
  text ".Layer_Name" at 577,-858.49 h60
Drill Guide:
  text ".Layer_Name" at 577,-858.49 h60
M1 Board Outline:
  the board outline again, w10
  text ".Layer_Name" at 577,-858.49 h60
M2 Board Dimensions:
  rectangle: 0,-275 125,-150
  rectangle: 125,-400 500,-275
  lines w7: 0,-275 1000,-275 ; 125,-400 125,-150 ; 250,-400 250,-150 ; 500,-400 500,-150 ; 750,-400 750,-150 ; 0,-400 1000,-400 1000,-150 0,-150 0,-400
  text ".Layer_Name" at 577,-858.49 h60
M3 3D STEP Top:
  text ".Layer_Name" at 577,-858.49 h60
M4 3D STEP Bottom:
  text ".Layer_Name" at 577,-858.49 h60
M5 Assembly Top:
  lines w10: -292,-930.17 6308,-930.17 ; -292,-726.83 6310,-726.83 ; -292,-523.5 -292,-1133.5 3713,-1133.5 6310,-1133.5 6310,-523.5 -291.5,-523.5 -291.5,-1133.5 1284,-1133.5 ; 2173,-1133.5 2173,-523.5 ; 3440,-726.83 3440,-523.5 ; 4280,-726.83 4280,-523.5 ; 4902,-1140 4902,-937.17
  text "COMPONENTS MARKED 'DNP' SHOULD NOT BE POPULATED." at 1153.5,-318.5 h60
  text "ASSEMBLY VARIANT:" at 1153,-434 h60
  text ".VariantName" at 2189,-434 h60
  text "PCB VIEWED FROM TOP SIDE" at -228.5,-655.67 h60
  text "BOARD #:" at 2248,-655.67 h60
  text ".PRJ_Number" at 2793.5,-655.67 h60
  text "REV:" at 3638,-655.67 h60
  text ".PCB_Rev" at 3929.5,-655.67 h60
  text "SVN REV:" at 4476,-655.67 h60
  text ".VersionControl_RevNumber" at 4982,-655.67 h60
  text "TID #:" at 2248,-859 h60
  text ".TID" at 2793.5,-859 h60
  text "PLOT NAME =" at -228.5,-1064.34 h60
  text ".plot_File_Name" at 577,-1064.34 h60
  text "GENERATED    :" at 2250,-1064.34 h60
  text ".Print_Date" at 3119.5,-1064.34 h60
  text ".Print_Time" at 3848.5,-1064.34 h60
  text "TEXAS INSTRUMENTS" at 5113,-1064.34 h60
M6 Assembly Bottom:
  lines w10: -292.5,-727.33 6309.5,-727.33 ; -290.5,-930.67 6309.5,-930.67 ; 1115.5,-1140.5 1115.5,-937.67 ; 1737.5,-727.33 1737.5,-524 ; 2577.5,-727.33 2577.5,-524 ; 3844.5,-1134 3844.5,-524 ; 4733.5,-1134 6309,-1134 6309,-524 -292.5,-524 -292.5,-1134 2304.5,-1134 6309.5,-1134 6309.5,-524
  text "COMPONENTS MARKED 'DNP' SHOULD NOT BE POPULATED." at 6102,-318 h60
  text ".VariantName" at 5058,-434 h60
  text "ASSEMBLY VARIANT:" at 6097,-434 h60
  text ".VersionControl_RevNumber" at 1035.5,-656.17 h60
  text "SVN REV:" at 1541.5,-656.17 h60
  text ".PCB_Rev" at 2088,-656.17 h60
  text "REV:" at 2379.5,-656.17 h60
  text ".PRJ_Number" at 3224,-656.17 h60
  text "BOARD #:" at 3769.5,-656.17 h60
  text "PCB VIEWED FROM BOTTOM SIDE" at 6246,-656.17 h60
  text ".TID" at 3224,-859.5 h60
  text "TID #:" at 3769.5,-859.5 h60
  text "TEXAS INSTRUMENTS" at 904.5,-1064.84 h60
  text ".Print_Time" at 2169,-1064.84 h60
  text ".Print_Date" at 2898,-1064.84 h60
  text "GENERATED    :" at 3767.5,-1064.84 h60
  text ".plot_File_Name" at 5440.5,-1064.84 h60
  text "PLOT NAME =" at 6246,-1064.84 h60
M9 Title Sheet:
  drawing of 57 lines, arcs and shapes, not listed
  text "1" at 739.84,8036.5 h70
  text "2" at 3235.5,8036.5 h70
  text "3" at 5724.84,8036.5 h70
  text "4" at 8231.51,8036.5 h70
  text "5" at 10730.5,8036.5 h70
  text "6" at 13235.5,8036.5 h70
  text "A" at -416.5,6893.5 h70
  text "A" at 14383.5,6893.5 h70
  text "B" at -416.5,4513.5 h70
  text "B" at 14383.5,4513.5 h70
  text "C" at -416.5,2138.5 h70
  text "C" at 14383.5,2138.5 h70
  text "PROJECT TITLE:" at 11343.5,277.5 h45
  text ".PRJ_Title" at 11393.5,144.17 h70
  text "DESIGNED FOR:" at 11343.5,-23.5 h45
  text ".PRJ_Customer" at 11393.5,-163.5 h70
  text "D" at -416.5,-231.5 h70
  text "D" at 14383.5,-231.5 h70
  text "FILE NAME:" at 11343.5,-323.5 h45
  text ".PCB_File_Name_No_Path" at 11393.5,-443.5 h70
  text "Texas Instruments (TI) and/or its licensors do not warrant the accuracy or completeness of this specification" at 6374,-605.34 h45
  text "ENGINEER:" at 11343.5,-613.5 h45
  text "LAYOUT BY:" at 12848.5,-613.5 h45
  text "or any information contained therein. TI and/or its licensors do not warrant that this design will meet" at 6329.01,-718 h45
  text ".PRJ_Engineer" at 11393.5,-768.49 h70
  text ".PCB_Layout" at 12899,-768.49 h70
  text "the specifications, will be suitable for your application or fit for any particular purpose, or will operate in" at 6329.01,-830.67 h45
  text ".Layer_Name" at 577,-858.49 h60
  text "ALTIUM DESIGNER VERSION:" at 12848.5,-923.5 h45
  text "an implementation. TI and/or its licensors do not warrant that the design is production worthy. You should" at 6329.01,-943.33 h45
  text "completely validate and test your design implementation to confirm the system functionality for your application." at 6374,-1056 h45
  text ".print_Scale" at 11393.5,-1056.83 h70
  text ".Application_BuildNumber" at 12899,-1056.83 h70
  text "1" at 739.84,-1263.5 h70
  text "2" at 3235.5,-1263.5 h70
  text "3" at 5724.84,-1263.5 h70
  text "4" at 8231.51,-1263.5 h70
  text "5" at 10730.5,-1263.5 h70
  text "6" at 13235.5,-1263.5 h70
M10 Fab Notes:
  drawing of 189 lines, arcs and shapes, not listed
  text "DESIGN INFORMATION" at 12382.02,6356.17 h60
  text "MIN. TRACK WIDTH:" at 11737.46,6224.05 h60
  text "8" at 12833.7,6224.05 h60
  text "MIL" at 12988.46,6224.05 h60
  text "MIN. CLEARANCE:" at 11737.46,6099.92 h60
  text "0.2" at 12773.7,6099.93 h60
  text "mm" at 12988.46,6099.92 h60
  text "MIN. VIA PAD SIZE:" at 11737.46,5975.8 h60
  text "24" at 12803.71,5975.8 h60
  text "MIL" at 12988.46,5975.8 h60
  text "0.05mm (2MIL)" at 12432.46,5845.9 h60
  text "MINIMUM ANNULAR RING" at 11408.23,5837.67 h60
  text "EXTERNAL" at 13140.46,5837.67 h60
  text "PER" at 11608.23,5727.55 h60
  text "IPC-D-275 CLASS 2 LEVEL C" at 11828.23,5727.54 h60
  text "MIL, HOLES" at 13316.46,5627.07 h60
  text "+/-" at 12924,5618.48 h60
  text "+/-" at 13778,5618.48 h60
  text "REGISTRATION TOLERANCES:" at 11408.23,5617.42 h60
  text "METAL" at 12608,5617.42 h60
  text "5" at 13184.2,5617.42 h60
  text "3" at 14017.2,5617.42 h60
  text "MIL" at 14133.46,5617.42 h60
  text "HOLE SIZE TOLERANCE (UNLESS OTHERWISE SPECIFIED):" at 11408.23,5519.1 h60
  text "+/-" at 13778,5516.23 h60
  text "3" at 14017.2,5515.17 h60
  text "MIL" at 14133.46,5515.17 h60
  text "MATERIAL:" at 11333.46,5377.52 h60
  text "FR-4 High Tg" at 12319.9,5249 h60
  text "X" at 12175.46,5241.01 h60
  text "FR-408" at 11754.46,5236.49 h60
  text "OTHER" at 13242.46,5236.49 h60
  text "62 MIL (1.6mm) +/-10%" at 12074.56,5093.46 h60
  text "X" at 11954.46,5091.01 h60
  text "THICKNESS:" at 11408.23,5085.24 h60
  text "OTHER" at 13359.46,5085.24 h60
  text "TOLERANCE:" at 11408.23,4946.92 h60
  text "X" at 12256.46,4946.92 h60
  text "ANSI IPC-6012 TYPE 3 CLASS 2" at 12434.48,4946.92 h60
  text "OTHER +/-" at 12434.46,4802.73 h60
  text "BOW & TWIST:" at 11408.23,4657.54 h60
  text "X" at 12256.46,4657.54 h60
  text "ANSI IPC-6012 TYPE 3 CLASS 2" at 12434.48,4657.54 h60
  text "OTHER +/-" at 12434.46,4510.85 h60
  text "DRILLING:" at 11333.46,4380.23 h60
  text "NC_DRILL FILES" at 13094.46,4275.04 h60
  text "REFERENCE:" at 11408.23,4271.1 h60
  text "X" at 12065.46,4271.01 h60
  text "AS SHOWN" at 12243.46,4271.1 h60
  text "X" at 12966.46,4271.1 h60
  text "OTHER" at 13392.46,4128.85 h60
  text "PTH COPPER THICKNESS:" at 11407.91,4125.32 h60
  text "X" at 12547.14,4125.32 h60
  text "20-30 um" at 12675.14,4125.32 h60
  text "BOARD FINISH:" at 11333.46,3977.73 h60
  text "SILKSCREEN:" at 11488.68,3867.6 h60
  text "X" at 12446.46,3867.6 h60
  text "TOP" at 12563.46,3867.6 h60
  text "X" at 12956.46,3867.6 h60
  text "BOTTOM" at 13074.46,3867.6 h60
  text "SILKSCREEN COLOR:" at 11488.68,3712.41 h60
  text "X" at 12445.46,3712.41 h60
  text "WHITE" at 12563.46,3712.41 h60
  text "OTHER" at 13074.46,3712.41 h60
  text "X" at 12576.46,3568.96 h60
  text "GREEN" at 12694.46,3568.96 h60
  text "OTHER" at 13312.46,3568.96 h60
  text "SOLDER RESIST COLOR:" at 11488.68,3562.1 h60
  text "X" at 12576.46,3414.71 h60
  text "MATTE" at 12694.46,3414.71 h60
  text "SEMI-GLOSS" at 13312,3414.07 h60
  text "IMMERSION GOLD (ENIG)" at 12394.46,3241.94 h60
  text "ENEPIG" at 13732,3234.72 h60
  text "SURFACE FINISH:" at 11333.46,3233.72 h60
  text "X" at 12216.46,3233.72 h60
  text "IMM. TIN/SILVER OR EQUIV" at 11663,3096.4 h60
  text "OTHER" at 13094.46,3092.47 h60
  text "ARRAY/PANEL:" at 11333.46,2937.09 h60
  text "CUT AND TRIM PER M1 BOARD OUTLINE" at 12394.46,2928.87 h60
  text "N.C. ROUTE" at 12394.46,2792.9 h60
  text "X" at 13082.46,2792.9 h60
  text "V. SCORE" at 13260.46,2792.9 h60
  text "CERTIFICATION:" at 11333.46,2663.77 h60
  text "MATERIALS AND WORKMANSHIP FOR ALL PCBS" at 12058.46,2663.77 h60
  text "TO MEET OR EXCEED THE REQUIREMENTS OF:" at 12058.46,2569.71 h60
  text "X" at 11695.97,2441.08 h60
  text "ANSI IPC-A-600F CLASS ->" at 11823.96,2441.08 h60
  text "X" at 13471.97,2441.08 h60
  text "2" at 13581.96,2441.08 h60
  text "1" at 13266.96,2439.58 h60
  text "3" at 13935.96,2439.58 h60
  text "X" at 12507.97,2293.39 h60
  text "RoHS" at 12635.96,2293.39 h60
  text "OTHER" at 13280.36,2293.39 h60
  text "PER ORDER" at 13677.42,2293.39 h60
  text "ALL BOARDS MUST MEET OR EXCEED UL94-V0 REQUIREMENTS." at 11361,2139.57 h60
  text "PCB MUST BEAR THE UL94V-0 UL REGISTERED MATERIAL ID NUMBER" at 11361,2023.5 h60
  text "ADDITIONAL REQUIREMENTS:" at 11333.46,1854.08 h60
  text "MICROSECTION:" at 11408.23,1746.95 h60
  text "YES" at 12313.96,1746.95 h60
  text "REQUIRED" at 13175.46,1602.62 h60
  text "BARE BOARD ELEC. TEST:" at 11408.23,1599.76 h60
  text "NONE" at 12713.96,1599.76 h60
  text "X" at 13057.46,1599.76 h60
  text "PER ORDER" at 13767.46,1599.76 h60
  text "XX MIL VIAS REQUIRE NON-CONDUCTIVE FILL AND PLANARIZE" at 11576.38,1394.82 h59
  text "XX MIL VIAS REQUIRE CONDUCTIVE FILL AND PLANARIZE" at 11584.38,1290.84 h60
  text "OUTER XX MIL TRACES REQUIRE 50 OHM SINGLE-ENDED IMPEDANCE" at 11583.39,1127.46 h58
  text "LAYER 2 & 3 (INNER LAYERS) XX MIL WIDE, XX MIL SPACE / TRACES REQUIRE 100 OHM DIFFERENTIAL IMPEDANCE" at 11575.39,891.74 h60
  text ".Layer_Name" at 577,-858.49 h60
M11 Gerber Information:
  lines w10: -292,-930.17 6308,-930.17 ; -292,-726.83 6310,-726.83 ; -292,-523.5 -292,-1133.5 3713,-1133.5 6310,-1133.5 6310,-523.5 -291.5,-523.5 -291.5,-1133.5 1284,-1133.5 ; 2173,-1133.5 2173,-523.5 ; 3440,-726.83 3440,-523.5 ; 4280,-726.83 4280,-523.5 ; 4902,-1140 4902,-937.17
  text "ALL ARTWORK VIEWED FROM TOP SIDE" at -228.5,-655.67 h60
  text "BOARD #:" at 2248,-655.67 h60
  text ".PRJ_Number" at 2793.5,-655.67 h60
  text "REV:" at 3638,-655.67 h60
  text ".PCB_Rev" at 3929.5,-655.67 h60
  text "SVN REV:" at 4476,-655.67 h60
  text ".VersionControl_RevNumber" at 4982,-655.67 h60
  text "LAYER NAME =" at -228.5,-858.49 h60
  text "TID #:" at 2248,-859 h60
  text ".TID" at 2793.5,-859 h60
  text "PLOT NAME =" at -228.5,-1064.34 h60
  text ".plot_File_Name" at 577,-1064.34 h60
  text "GENERATED    :" at 2250,-1064.34 h60
  text ".Print_Date" at 3119.5,-1064.34 h60
  text ".Print_Time" at 3848.5,-1064.34 h60
  text "TEXAS INSTRUMENTS" at 5113,-1064.34 h60
M12 Stackup:
  text ".Layer_Name" at 577,-858.49 h60
M13 Component Bodies Top:
  text ".Layer_Name" at 577,-858.49 h60
M14 Component Bodies Bottom:
  text ".Layer_Name" at 577,-858.49 h60
M15 Courtyards Top:
  text ".Layer_Name" at 577,-858.49 h60
M16 Courtyards Bottom:
  text ".Layer_Name" at 577,-858.49 h60
Drill Drawing:
  text ".Layer_Name" at 577,-858.49 h60
M17 Embedded Cavity:
  text ".Layer_Name" at 577,-858.49 h60
M18 Embedded Assembly:
  text ".Layer_Name" at 577,-858.49 h60
M19 Embedded Keepout:
  text ".Layer_Name" at 577,-858.49 h60

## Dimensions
0,-400 to 1000,-400 on M2 Board Dimensions
0,0 to 0,3750 on M2 Board Dimensions
0,0 to 3287.4,0 on M2 Board Dimensions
